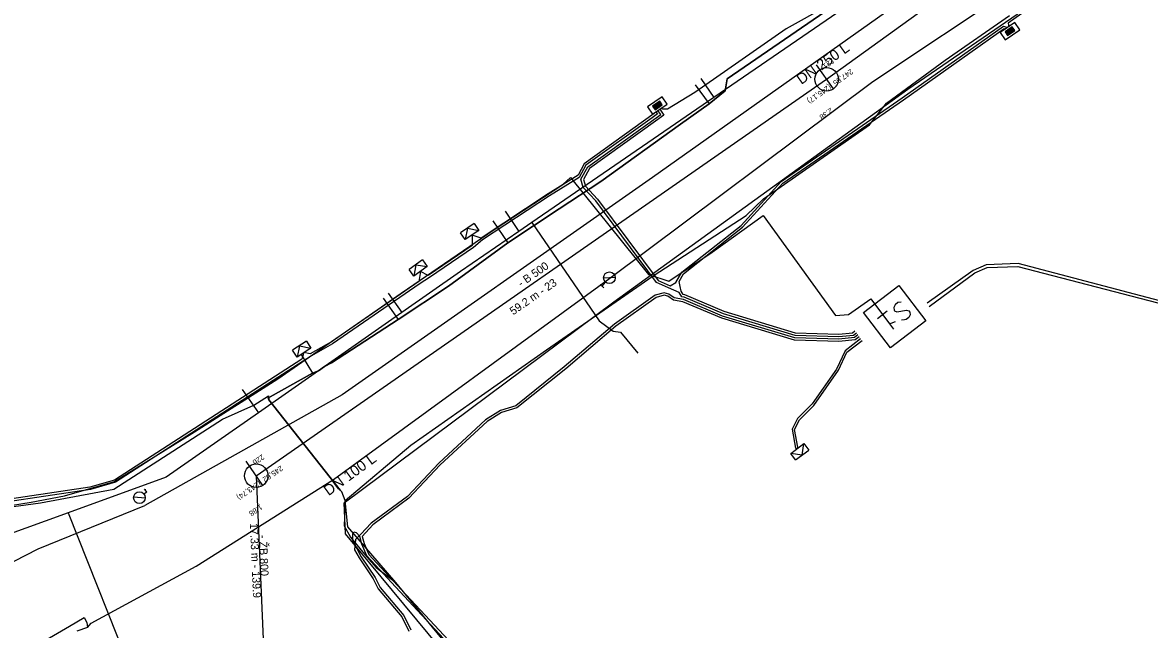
# Model space of a CAD drawing. Extents: x -600636 to -600148, y -1203980 to -1203569.
# Drawn here: x -600579.1 to -600483.1, y -1203791.8 to -1203740.1 of the extents above; entities that cross this region are included whole.
import ezdxf

# ---------------------------------------------------------------- set-up
doc = ezdxf.new("R2010")
doc.units = 0
for name, color, linetype in [('Cetin zam průběh', 7, 'Continuous'), ('EON objekty', 7, 'Continuous'), ('EON podzemní NN', 7, 'Continuous'), ('EON podzemní VN', 7, 'Continuous'), ('GasNet NTL', 7, 'Continuous'), ('Implicitní', 7, 'Continuous'), ('VaK Břeclav_kanalizace', 7, 'Continuous'), ('VaK Břeclav_kanalizace_popis', 7, 'Continuous'), ('Vak Břeclav_vodovod', 7, 'Continuous'), ('Vak Břeclav_vodovod_popis', 7, 'Continuous'), ('Vrstva 6', 7, 'Continuous'), ('Vrstva 9', 7, 'Continuous')]:
    doc.layers.add(name, color=color, linetype=linetype)

# ---------------------------------------------------------------- blocks, each defined once
blk = doc.blocks.new('NN630')
at = {"layer": 'Vrstva 9'}
for points in [[(-0.003, -0.7), (-0.703, 0)], [(-0.703, -0.7), (-0.703, 0), (0.697, 0), (0.697, -0.7)], [(-0.703, -0.7), (0.697, -0.7)], [(-0.003, -0.7), (0.697, 0)]]:
    blk.add_lwpolyline(points, dxfattribs=at)
blk = doc.blocks.new('NN620')
at = {"layer": 'EON objekty'}
for points in [[(0.752, 0.004), (-0.748, 0.004)], [(-0.748, 0.004), (-0.748, -0.746)], [(0.752, -0.746), (0.752, 0.004)], [(-0.748, -0.746), (0.752, -0.746)], [(0.368, -0.18), (-0.376, -0.18)], [(-0.376, -0.18), (-0.376, -0.558)], [(-0.376, -0.558), (0.368, -0.558)], [(0.321, -0.227), (-0.329, -0.227)], [(-0.329, -0.227), (-0.329, -0.51)], [(-0.329, -0.51), (0.321, -0.51)], [(0.274, -0.274), (-0.281, -0.274)], [(-0.281, -0.274), (-0.281, -0.463)], [(-0.281, -0.463), (0.274, -0.463)], [(0.227, -0.321), (-0.234, -0.321)], [(-0.234, -0.321), (-0.234, -0.416)], [(-0.234, -0.416), (0.227, -0.416)], [(-0.193, -0.369), (0.185, -0.369)], [(0.227, -0.416), (0.227, -0.321)], [(0.274, -0.463), (0.274, -0.274)], [(0.321, -0.51), (0.321, -0.227)], [(0.368, -0.558), (0.368, -0.18)]]:
    blk.add_lwpolyline(points, dxfattribs=at)
blk = doc.blocks.new('VN640')
at = {"layer": 'Vrstva 6'}
for points in [[(-1.89, 1.889), (1.889, 1.889)], [(-1.89, -1.89), (-1.89, 1.889)], [(1.889, 1.889), (1.889, -1.89)], [(-1.26, 0.787), (-0.221, 0.787)], [(-0.725, 0.787), (-0.725, -0.788)], [(1.197, 0.661), (0.945, 0.787), (0.661, 0.787), (0.409, 0.661), (0.283, 0.472), (0.283, 0.409), (0.409, 0.22), (1.133, -0.158), (1.259, -0.316), (1.259, -0.473), (1.133, -0.662), (0.913, -0.788), (0.629, -0.788), (0.503, -0.725), (0.283, -0.599)], [(1.889, -1.89), (-1.89, -1.89)]]:
    blk.add_lwpolyline(points, dxfattribs=at)
blk = doc.blocks.new('MoSymbol 2')
at = {"layer": 'Implicitní'}
blk.add_line((0, 0.0005), (0, -0.00075), dxfattribs=at)
blk.add_circle((0, 0), 0.0005, dxfattribs=at)
blk = doc.blocks.new('MoSymbol 3')
at = {"layer": 'Implicitní'}
for p, q in [((-0.000365, -0.000365), (0.000365, 0.000365)), ((-0.000225, 0.00095), (0.000225, 0.00095)), ((0, 0.00095), (0, 0.0005))]:
    blk.add_line(p, q, dxfattribs=at)
blk.add_circle((0, 0), 0.0005, dxfattribs=at)
blk = doc.blocks.new('MoSymbol 4')
at = {"layer": 'Implicitní'}
for p, q in [((-0.000365, -0.000365), (0.000365, 0.000365)), ((0.0003, -0.0008), (0.0002, -0.00085))]:
    blk.add_line(p, q, dxfattribs=at)
blk.add_lwpolyline([(0, -0.0005), (0, -0.0008), (0.0003, -0.0008), (0.0002, -0.00075)], dxfattribs=at)
blk.add_circle((0, 0), 0.0005, dxfattribs=at)

msp = doc.modelspace()

# ---------------------------------------------------------------- linework, layer by layer
at = {"layer": 'Cetin zam průběh'}
for points in [[(-600506.23, -1203736.22), (-600510.74, -1203739.23), (-600519.05, -1203744.93), (-600519.22, -1203745.96), (-600520.6, -1203747.08), (-600523.03, -1203748.81), (-600529.84, -1203753.68), (-600533.39, -1203756), (-600537.76, -1203758.9), (-600542.81, -1203762.61), (-600547.1, -1203765.43), (-600552.78, -1203769.13), (-600553.37, -1203769.45), (-600553.89, -1203769.82), (-600554.42, -1203770.01), (-600558.01, -1203772.02)], [(-600499.06, -1203830.56), (-600501.19, -1203829.34), (-600520.52, -1203816.59), (-600528.18, -1203809.84), (-600537.51, -1203800.68), (-600551.58, -1203783.7), (-600551.71, -1203781.06), (-600528.73, -1203763.94), (-600503.65, -1203745.81), (-600492.34, -1203738.04), (-600490.82, -1203737.26)], [(-600551.61, -1203780.87), (-600546.02, -1203776.14), (-600534.46, -1203768.01), (-600525.37, -1203761.73), (-600517.43, -1203756.57), (-600515.95, -1203755.15), (-600506.94, -1203748.87), (-600505.47, -1203747), (-600500.48, -1203743.35), (-600495, -1203739.53)], [(-600520.6, -1203747.08), (-600519.22, -1203745.96), (-600519.05, -1203744.93), (-600510.74, -1203739.23)], [(-600521.78, -1203745.45), (-600520.6, -1203747.08)], [(-600537.76, -1203758.9), (-600533.39, -1203756), (-600529.84, -1203753.68), (-600523.03, -1203748.81), (-600520.6, -1203747.08)], [(-600539.032, -1203757.042), (-600537.76, -1203758.9)], [(-600547.1, -1203765.43), (-600542.81, -1203762.61), (-600537.76, -1203758.9)], [(-600548.377, -1203763.622), (-600547.1, -1203765.43)], [(-600553.37, -1203769.45), (-600552.78, -1203769.13), (-600547.1, -1203765.43)], [(-600555.386, -1203768.434), (-600554.42, -1203770.01)], [(-600558.18, -1203772.12), (-600558.01, -1203772.02), (-600554.42, -1203770.01)], [(-600554.42, -1203770.01), (-600553.89, -1203769.82), (-600553.37, -1203769.45)], [(-600587.64, -1203782.42), (-600577.59, -1203781.05), (-600571.34, -1203779.9), (-600562.09, -1203773.93), (-600559.42, -1203772.74), (-600558.16, -1203771.94), (-600558.14, -1203772.28)], [(-600558.14, -1203772.28), (-600558.18, -1203772.12)], [(-600558.14, -1203772.28), (-600552.05, -1203779.98)], [(-600551.61, -1203780.87), (-600551.92, -1203780.12), (-600552.05, -1203779.98), (-600558.14, -1203772.28)], [(-600577.59, -1203781.05), (-600571.34, -1203779.9)], [(-600551.61, -1203780.87), (-600551.71, -1203783.02)], [(-600547.3, -1203787.83), (-600551.39, -1203783.09), (-600551.61, -1203780.87)], [(-600551.71, -1203783.02), (-600551.17, -1203783.97)], [(-600551.17, -1203783.97), (-600549.98, -1203785.44)], [(-600549.98, -1203785.44), (-600548.99, -1203786.57)], [(-600548.99, -1203786.57), (-600547.3, -1203787.83)], [(-600531.56, -1203806.25), (-600532.29, -1203804.48), (-600533.68, -1203802.64), (-600539.8, -1203796.23), (-600541.55, -1203794.83), (-600547.3, -1203787.83)]]:
    msp.add_lwpolyline(points, dxfattribs=at)
at = {"layer": 'EON podzemní NN'}
for points in [[(-600492.79, -1203738.54), (-600495.12, -1203740.2), (-600495.048, -1203740.497)], [(-600510.522, -1203738.712), (-600514.041, -1203740.671), (-600521.805, -1203746.093), (-600524.15, -1203747.521), (-600524.559, -1203747.517), (-600524.638, -1203747.401)], [(-600524.803, -1203747.515), (-600524.45, -1203748.027), (-600525.161, -1203748.537), (-600530.795, -1203752.578), (-600531.314, -1203753.511), (-600531.149, -1203754.093), (-600530.101, -1203755.202), (-600524.951, -1203762.125), (-600523.912, -1203762.574), (-600523.438, -1203762.281), (-600522.938, -1203761.404), (-600517.882, -1203757.418), (-600514.454, -1203753.685), (-600504.155, -1203746.549), (-600495.501, -1203740.461), (-600495.161, -1203740.575)], [(-600508.174, -1203766.439), (-600508.374, -1203766.595), (-600509.556, -1203766.723), (-600513.237, -1203766.614), (-600519.313, -1203764.765), (-600522.658, -1203763.34), (-600522.814, -1203763.315), (-600522.985, -1203763.029), (-600523.058, -1203762.627), (-600523.155, -1203762.189), (-600522.784, -1203761.536), (-600517.746, -1203757.566), (-600514.322, -1203753.837), (-600504.041, -1203746.713), (-600495.441, -1203740.663), (-600495.347, -1203740.703)], [(-600525.132, -1203747.742), (-600525.004, -1203747.932), (-600525.449, -1203748.251), (-600531.101, -1203752.305), (-600531.678, -1203753.342), (-600534.216, -1203754.907), (-600539.903, -1203758.664), (-600540.687, -1203759.293), (-600544.438, -1203761.852), (-600545.238, -1203762.368), (-600552.695, -1203767.501), (-600554.501, -1203768.539), (-600555.203, -1203768.985), (-600571.205, -1203779.307), (-600573.331, -1203779.913), (-600584.423, -1203781.578), (-600586.99, -1203781.825)], [(-600525.297, -1203747.856), (-600525.279, -1203747.883), (-600531.254, -1203752.169), (-600531.757, -1203753.151), (-600534.324, -1203754.739), (-600540.021, -1203758.502), (-600540.809, -1203758.243), (-600540.807, -1203759.133), (-600544.548, -1203761.686), (-600545.191, -1203761.339), (-600545.348, -1203762.202), (-600552.801, -1203767.331), (-600554.605, -1203768.367), (-600555.135, -1203768.259), (-600555.311, -1203768.817), (-600571.289, -1203779.123), (-600573.373, -1203779.717), (-600584.447, -1203781.38), (-600586.729, -1203781.599)], [(-600508.051, -1203766.597), (-600508.296, -1203766.788), (-600509.548, -1203766.923), (-600513.27, -1203766.813), (-600519.381, -1203764.953), (-600522.714, -1203763.534), (-600522.937, -1203763.499), (-600523.15, -1203763.143), (-600524.054, -1203762.728), (-600525.079, -1203762.287), (-600530.255, -1203755.33), (-600531.329, -1203754.195), (-600531.529, -1203753.485), (-600530.948, -1203752.441), (-600524.726, -1203747.979), (-600524.968, -1203747.629)], [(-600507.93, -1203766.757), (-600508.218, -1203766.98), (-600509.54, -1203767.123), (-600513.302, -1203767.013), (-600519.449, -1203765.141), (-600522.77, -1203763.728), (-600523.568, -1203763.602), (-600524.04, -1203763.278), (-600524.429, -1203763.174), (-600525.201, -1203763.374), (-600528.66, -1203765.841), (-600532.953, -1203769.48), (-600537.072, -1203772.794), (-600538.387, -1203773.179), (-600539.651, -1203773.979), (-600543.651, -1203777.673), (-600546.318, -1203780.515), (-600549.403, -1203782.78), (-600550.274, -1203783.739), (-600550.742, -1203784.175), (-600550.814, -1203785.049), (-600550.442, -1203785.747), (-600549.233, -1203787.52), (-600548.817, -1203788.369), (-600546.802, -1203790.768), (-600546.203, -1203791.975)], [(-600507.807, -1203766.914), (-600508.14, -1203767.173), (-600509.532, -1203767.323), (-600513.335, -1203767.212), (-600519.517, -1203765.329), (-600522.826, -1203763.922), (-600523.644, -1203763.792), (-600524.125, -1203763.462), (-600524.429, -1203763.38), (-600525.115, -1203763.558), (-600528.538, -1203765.999), (-600532.825, -1203769.634), (-600536.978, -1203772.974), (-600538.303, -1203773.363), (-600539.529, -1203774.139), (-600543.511, -1203777.815), (-600546.184, -1203780.665), (-600549.269, -1203782.93), (-600550.165, -1203783.917), (-600550.015, -1203784.513), (-600549.597, -1203785.445), (-600546.825, -1203788.464), (-600540.809, -1203794.912)], [(-600507.684, -1203767.072), (-600509.013, -1203768.103), (-600509.737, -1203769.669), (-600511.828, -1203772.631), (-600513.052, -1203773.88), (-600513.528, -1203774.769), (-600513.229, -1203776.405), (-600513.085, -1203776.425), (-600513.041, -1203776.319), (-600513.318, -1203774.801), (-600512.89, -1203774), (-600511.674, -1203772.759), (-600509.563, -1203769.769), (-600508.852, -1203768.232), (-600507.561, -1203767.229)], [(-600540.961, -1203795.042), (-600546.971, -1203788.6), (-600549.767, -1203785.557), (-600550.205, -1203784.579), (-600550.366, -1203783.937), (-600550.644, -1203783.623), (-600550.862, -1203783.55), (-600550.993, -1203783.691), (-600551.002, -1203784.225), (-600550.27, -1203785.645), (-600549.059, -1203787.42), (-600548.649, -1203788.259), (-600546.634, -1203790.658), (-600546.033, -1203791.869)]]:
    msp.add_lwpolyline(points, dxfattribs=at)
at = {"layer": 'EON podzemní VN'}
for points in [[(-600587.683, -1203782.424), (-600583.35, -1203781.8), (-600578.39, -1203781.01), (-600575.54, -1203780.47), (-600571.28, -1203779.25), (-600564.47, -1203775), (-600557.37, -1203770.49), (-600546.85, -1203763.19), (-600538.93, -1203757.78), (-600533.07, -1203753.94), (-600532.42, -1203753.34), (-600525.77, -1203761.6), (-600524.04, -1203762.18), (-600520.34, -1203759.69), (-600515.99, -1203756.58), (-600509.828, -1203765.1), (-600508.705, -1203765.014), (-600506.819, -1203763.668), (-600505.22, -1203765.813), (-600504.7, -1203765.596)], [(-600480.143, -1203764.381), (-600494.25, -1203760.681), (-600496.996, -1203760.787), (-600498.081, -1203761.253), (-600502, -1203764.039)], [(-600501.847, -1203764.325), (-600497.959, -1203761.475), (-600496.908, -1203761.001), (-600494.282, -1203760.923), (-600480.162, -1203764.577), (-600479.132, -1203764.829), (-600476.382, -1203766.071), (-600473.11, -1203766.482), (-600465.75, -1203768.323), (-600457.511, -1203769.594), (-600456.508, -1203769.518), (-600454.624, -1203770.445), (-600451.211, -1203771.488), (-600448.233, -1203771.815), (-600444.486, -1203774.019), (-600442.217, -1203775.59), (-600438.167, -1203778.496), (-600424.472, -1203787.735), (-600416.801, -1203792.528), (-600411.123, -1203796.487), (-600404.975, -1203801.537), (-600404.82, -1203801.644), (-600404.96, -1203802.62)]]:
    msp.add_lwpolyline(points, dxfattribs=at)
at = {"layer": 'GasNet NTL'}
for points in [[(-600486.68, -1203722.48), (-600489.25, -1203724.39), (-600497.78, -1203730.73), (-600501.03, -1203733.15), (-600504.95, -1203736.06), (-600509.64, -1203739.28), (-600520.2, -1203746.52), (-600535.72, -1203757.18), (-600536.81, -1203757.93), (-600541.8, -1203761.35), (-600546.79, -1203764.85), (-600559, -1203773.38), (-600566.88, -1203778.88), (-600575.24, -1203781.91), (-600588.36, -1203786.65), (-600589.51, -1203786.96)], [(-600521.31, -1203744.92), (-600520.2, -1203746.52)], [(-600537.99, -1203756.21), (-600536.81, -1203757.93)], [(-600535.72, -1203757.18), (-600529.98, -1203765.55), (-600528.77, -1203766.42), (-600528.15, -1203766.53), (-600526.67, -1203768.32)], [(-600547.95, -1203763.19), (-600546.79, -1203764.85)], [(-600560.39, -1203771.4), (-600559, -1203773.38)], [(-600575.24, -1203781.91), (-600569.42, -1203796.55), (-600565.52, -1203798.53), (-600556.3, -1203803.23), (-600544.92, -1203810.5), (-600533.6, -1203818.43), (-600528.85, -1203821.76), (-600523.82, -1203825.28), (-600521.43, -1203826.96)]]:
    msp.add_lwpolyline(points, dxfattribs=at)
at = {"layer": 'VaK Břeclav_kanalizace'}
for p, q in [((-600510.583, -1203744.976), (-600486.459, -1203727.53)), ((-600559.203, -1203778.746), (-600510.583, -1203744.976)), ((-600559.203, -1203778.746), (-600558.458, -1203796.062))]:
    msp.add_line(p, q, dxfattribs=at)
at = {"layer": 'Vak Břeclav_vodovod'}
msp.add_line((-600573.583, -1203791.689), (-600574.494, -1203791.995), dxfattribs=at)
for points in [[(-600454.254, -1203701.013), (-600472.203, -1203715.152), (-600488.658, -1203727.344), (-600496.91, -1203733.124), (-600525.432, -1203753.341), (-600551.886, -1203771.847), (-600568.695, -1203781.296)], [(-600529.075, -1203761.905), (-600506.647, -1203745.162), (-600494.673, -1203737.188), (-600466.586, -1203717.369), (-600450.006, -1203704.697)], [(-600573.583, -1203791.689), (-600573.278, -1203791.312), (-600564.325, -1203786.439), (-600552.62, -1203779.071), (-600529.075, -1203761.905)], [(-600612.162, -1203773.201), (-600602.995, -1203784.637), (-600601.189, -1203803.343), (-600600.899, -1203803.294), (-600597.986, -1203803.077), (-600584.599, -1203797.079), (-600575.117, -1203791.572), (-600573.857, -1203790.834), (-600573.636, -1203791.26), (-600573.583, -1203791.689)], [(-600600.849, -1203803.933), (-600600.899, -1203803.294), (-600601.584, -1203796.186), (-600600.078, -1203795.751), (-600587.99, -1203790.2), (-600577.783, -1203784.972), (-600568.695, -1203781.296)]]:
    msp.add_lwpolyline(points, dxfattribs=at)

# ---------------------------------------------------------------- block references
at = {"layer": 'EON podzemní NN'}
for name, p, rotation in [('NN620', (-600495.16, -1203740.575), 34.499191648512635), ('NN620', (-600524.804, -1203747.514), -145.40948332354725), ('NN630', (-600540.809, -1203758.243), -145.68219166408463), ('NN630', (-600545.191, -1203761.339), -144.19583613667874), ('NN630', (-600555.135, -1203768.259), -146.84598330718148), ('NN630', (-600513.085, -1203776.425), 36.87192492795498)]:
    msp.add_blockref(name, p, dxfattribs=dict(at, rotation=rotation))
at = {"layer": 'EON podzemní VN', "rotation": 37.35362222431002}
msp.add_blockref('VN640', (-600504.779, -1203765.202), dxfattribs=at)
at = {"layer": 'VaK Břeclav_kanalizace'}
for p, xscale, yscale, rotation in [((-600510.583, -1203744.976), 1999.750031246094, 1999.7500312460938, -144.72778475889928), ((-600559.203, -1203778.746), 1999.7500312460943, 1999.7500312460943, -145.4726226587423)]:
    msp.add_blockref('MoSymbol 2', p, dxfattribs=dict(at, xscale=xscale, yscale=yscale, rotation=rotation))
at = {"layer": 'Vak Břeclav_vodovod'}
for name, p, xscale, yscale, rotation in [('MoSymbol 3', (-600529.097, -1203761.885), 999.875015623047, 999.8750156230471, 138.37882730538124), ('MoSymbol 4', (-600569.159, -1203780.618), 999.8750156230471, 999.875015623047, 129.01940047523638)]:
    msp.add_blockref(name, p, dxfattribs=dict(at, xscale=xscale, yscale=yscale, rotation=rotation))

# ---------------------------------------------------------------- texts
at = {"layer": 'VaK Břeclav_kanalizace_popis'}
for s, height, rotation, p in [('221', 0.4549, 215.27222, (-600510.132, -1203743.157)), ('247,55  (245,17)', 0.45494, 215.27222, (-600508.529, -1203744.066)), ('2.38', 0.4549, 215.27222, (-600510.253, -1203747.385)), ('- B 500', 0.6824, 34.78271, (-600536.621, -1203762.71)), ('59.2 m - 23', 0.68241, 34.78271, (-600537.3, -1203765.094)), ('22b', 0.4549, 214.52738, (-600558.703, -1203776.902)), ('245,62  (243,74)', 0.45494, 214.52738, (-600557.123, -1203777.863)), ('1.88', 0.4549, 214.52738, (-600558.863, -1203781.16)), ('17.33 m - 139.9', 0.68241, 272.46301, (-600559.746, -1203782.79)), ('- ŽB 800', 0.6824, 272.46301, (-600558.973, -1203783.805))]:
    msp.add_text(s, height=height, rotation=rotation, dxfattribs=at).set_placement(p)
at = {"layer": 'Vak Břeclav_vodovod_popis'}
for s, rotation, p in [('DN 250 L', 35.32983, (-600512.741, -1203745.461)), ('DN 100 L', 36.09474, (-600553.032, -1203780.497))]:
    msp.add_text(s, height=0.9099, rotation=rotation, dxfattribs=at).set_placement(p)

doc.saveas('drawing.dxf')
